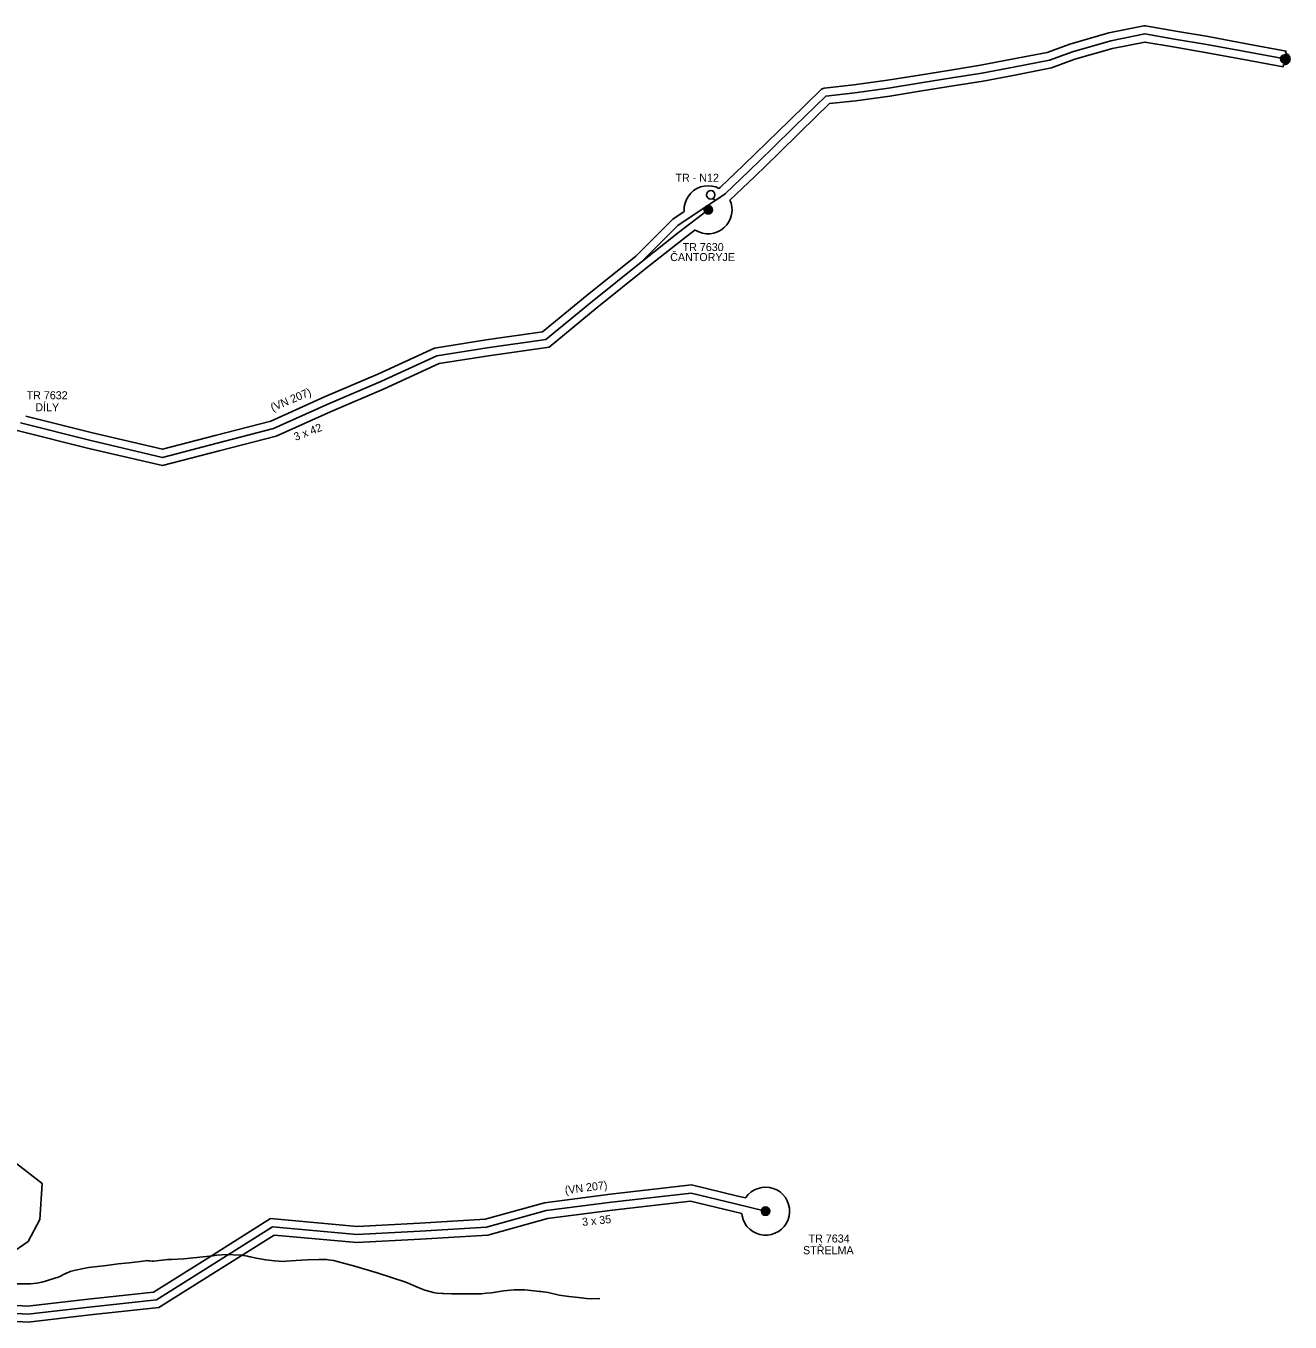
# Model space of a CAD drawing. Extents: x -439095 to -431527, y -1129525 to -1119219.
# Drawn here: x -436616 to -435036, y -1124332 to -1122712 of the extents above; entities that cross this region are included whole.
import ezdxf

# ---------------------------------------------------------------- set-up
doc = ezdxf.new("R2010")
doc.units = 0
for name, color, linetype in [('Hranice reseneho uzemi', 7, 'Continuous'), ('UZEMNI REZERVA', 7, 'Continuous'), ('Vrstva 11', 7, 'Continuous'), ('Vrstva 13', 7, 'Continuous'), ('Vrstva 19', 7, 'Continuous'), ('Vrstva 21', 7, 'Continuous'), ('ZU', 7, 'Continuous')]:
    doc.layers.add(name, color=color, linetype=linetype)

msp = doc.modelspace()

# ---------------------------------------------------------------- linework, layer by layer
at = {"layer": 'Hranice reseneho uzemi'}
msp.add_line((-435755, -1122930.5), (-435757.4, -1122927.6), dxfattribs=at)
for points in [[(-436622.9, -1123208.4), (-436534.9, -1123230.5), (-436445.4, -1123251.4), (-436377.2, -1123233.7), (-436306.5, -1123215.5), (-436238.7, -1123184.8), (-436172.3, -1123156.7), (-436102.5, -1123124.5), (-436039.5, -1123114.6), (-435966.2, -1123104.2), (-435908.5, -1123056.6), (-435847.3, -1123007.3), (-435845.2, -1123005.2), (-435801.3, -1122961.6), (-435742.2, -1122921.9), (-435712.2, -1122893.3), (-435683.2, -1122864.8), (-435655, -1122837.5), (-435616.5, -1122799.8), (-435616.3, -1122799.8), (-435580.4, -1122795.7), (-435538, -1122789.9), (-435497.9, -1122783.5), (-435459.1, -1122777.2), (-435421.4, -1122771.3), (-435382, -1122763.7), (-435337, -1122755), (-435308.3, -1122744.4), (-435260.5, -1122730.7), (-435218, -1122722.2), (-435217.8, -1122722.2), (-435180.8, -1122728.6), (-435140.5, -1122735.3), (-435092.5, -1122744.2), (-435043.1, -1122753.5)], [(-435847.3, -1123007.3), (-435800.4, -1122970.3), (-435800.4, -1122970.3), (-435763.3, -1122942)], [(-436699.2, -1124317.2), (-436613.5, -1124322.2), (-436537, -1124313.4), (-436453, -1124304.5), (-436383.4, -1124260.8), (-436308, -1124213.1), (-436202.3, -1124222.7), (-436123.4, -1124218.6), (-436040.6, -1124213.5), (-435966.1, -1124192.9), (-435884.3, -1124182.3), (-435784.9, -1124171), (-435729.4, -1124184.3), (-435729.4, -1124184.3), (-435691.8, -1124193.6), (-435691.5, -1124193.6), (-435691.5, -1124193.7)]]:
    msp.add_lwpolyline(points, dxfattribs=at)
at = {"layer": 'UZEMNI REZERVA'}
for points in [[(-436726.1, -1124283.9), (-436724.3, -1124276.9), (-436695.8, -1124271.9), (-436635.9, -1124247.3), (-436613.3, -1124231.5), (-436598.6, -1124204.1), (-436595.7, -1124158.9), (-436642.5, -1124122.7), (-436670.9, -1124104.1), (-436665.5, -1124056.1), (-436673.1, -1124038.1), (-436655, -1123989.1)], [(-436627.1, -1124284.4), (-436610.3, -1124284.5), (-436602.4, -1124283.6), (-436596.3, -1124282.3), (-436591.7, -1124281.1), (-436587.8, -1124279.8), (-436574.5, -1124275.5), (-436566.5, -1124271.7), (-436566.1, -1124271.5), (-436560.6, -1124269.2), (-436554, -1124267.3), (-436546, -1124265.6), (-436537.6, -1124264.2), (-436515.1, -1124261.4), (-436500.6, -1124259.6), (-436486.8, -1124258), (-436473, -1124256.5), (-436464.1, -1124255.4), (-436463.4, -1124255.5), (-436461.3, -1124255.7), (-436458.2, -1124256.2), (-436456.2, -1124255.9), (-436439, -1124254.2), (-436434.2, -1124253.9), (-436418.6, -1124253), (-436382.6, -1124249.3), (-436377.5, -1124248.8), (-436365.2, -1124247.9), (-436348.7, -1124248.4), (-436346.8, -1124248.7), (-436339.1, -1124249.9), (-436336, -1124250.7), (-436335.2, -1124250.8), (-436328.3, -1124252.4), (-436316.2, -1124254.6), (-436305.4, -1124255.8), (-436293.8, -1124256.6), (-436290.4, -1124256.3), (-436290.4, -1124256.3), (-436278.2, -1124255.4), (-436278.1, -1124255.4), (-436271.5, -1124254.9), (-436264.3, -1124254.4), (-436250, -1124254.2), (-436246.5, -1124254.2), (-436240.2, -1124254.1), (-436238.3, -1124254.3), (-436231.6, -1124255.2), (-436206.7, -1124261.8), (-436177.2, -1124270.8), (-436175.9, -1124271.2), (-436141.1, -1124282.5), (-436125.7, -1124289.1), (-436117.6, -1124292.2), (-436109.7, -1124294.6), (-436107.1, -1124295.1), (-436102.1, -1124296.1), (-436095.7, -1124296.7), (-436093.9, -1124296.6), (-436084.2, -1124296.9), (-436072.3, -1124297), (-436060.2, -1124297.1), (-436047.2, -1124297), (-436040.5, -1124296.2), (-436034.4, -1124295.5), (-436019.3, -1124293.3), (-436005.9, -1124292.1), (-435993, -1124292.1), (-435981.1, -1124293.3), (-435974.4, -1124294), (-435972.4, -1124294.2), (-435963.3, -1124295.3), (-435949.8, -1124298.4), (-435937.5, -1124300.4), (-435925.6, -1124301.5), (-435915.6, -1124302.6), (-435908.7, -1124303.1), (-435898.7, -1124302.7)]]:
    msp.add_lwpolyline(points, dxfattribs=at)
at = {"layer": 'Vrstva 11'}
for centre, radius in [((-435043.1, -1122753.4), 5.25), ((-435043.1, -1122753.4), 4.55), ((-435043.1, -1122753.4), 3.85), ((-435043.1, -1122753.4), 3.15), ((-435043.1, -1122753.4), 2.45), ((-435043.1, -1122753.4), 1.75), ((-435043.1, -1122753.4), 1.05), ((-435043.1, -1122753.4), 0.35), ((-435763.3, -1122942), 5.25), ((-435763.3, -1122942), 4.55), ((-435763.3, -1122942), 3.85), ((-435763.3, -1122942), 3.15), ((-435763.3, -1122942), 2.45), ((-435763.3, -1122942), 1.75), ((-435763.3, -1122942), 1.05), ((-435763.3, -1122942), 0.35), ((-435691.7, -1124193.6), 5.25), ((-435691.7, -1124193.6), 4.55), ((-435691.7, -1124193.6), 3.85), ((-435691.7, -1124193.6), 3.15), ((-435691.7, -1124193.6), 2.45), ((-435691.7, -1124193.6), 1.75), ((-435691.7, -1124193.6), 1.05), ((-435691.7, -1124193.6), 0.35)]:
    msp.add_circle(centre, radius, dxfattribs=at)
at = {"layer": 'Vrstva 19'}
msp.add_circle((-435760.3, -1122923.3), 5.25, dxfattribs=at)
at = {"layer": 'ZU'}
for points in [[(-435750.2, -1122915.2), (-435748.5, -1122914.1), (-435719.2, -1122886.1), (-435690.1, -1122857.7), (-435662, -1122830.3), (-435621.9, -1122791.1), (-435618.5, -1122789.9), (-435581.6, -1122785.8), (-435539.5, -1122780), (-435499.5, -1122773.6), (-435460.7, -1122767.3), (-435423.2, -1122761.4), (-435383.9, -1122753.9), (-435339.7, -1122745.4), (-435311.4, -1122734.9), (-435262.8, -1122721), (-435219, -1122712.2), (-435217, -1122712.2), (-435179.1, -1122718.8), (-435138.8, -1122725.5), (-435090.7, -1122734.4), (-435041.3, -1122743.6), (-435041.9, -1122746.7)], [(-435044.4, -1122760.4), (-435045, -1122763.3), (-435094.3, -1122754.1), (-435142.3, -1122745.2), (-435182.5, -1122738.5), (-435217.8, -1122732.3), (-435258.1, -1122740.5), (-435305.2, -1122753.9), (-435334.3, -1122764.7), (-435380.1, -1122773.6), (-435419.7, -1122781.1), (-435457.5, -1122787.1), (-435496.3, -1122793.4), (-435536.5, -1122799.8), (-435579.1, -1122805.6), (-435611.9, -1122809.3), (-435648, -1122844.6), (-435676.2, -1122872), (-435705.3, -1122900.5), (-435735.9, -1122929.7), (-435736.2, -1122929.9)], [(-435041.9, -1122746.7), (-435041, -1122746.9), (-435039.9, -1122747.4), (-435038.9, -1122748.1), (-435038, -1122749), (-435037.3, -1122750), (-435036.8, -1122751.1), (-435036.5, -1122752.3), (-435036.4, -1122753.5), (-435036.5, -1122754.7), (-435036.8, -1122755.9), (-435037.3, -1122757), (-435038, -1122758), (-435038.9, -1122758.9), (-435039.9, -1122759.6), (-435041, -1122760.1), (-435042.2, -1122760.4), (-435043.4, -1122760.5), (-435044.4, -1122760.4)], [(-435793.4, -1122944.3), (-435793.5, -1122943.2), (-435793.3, -1122938.4), (-435792.4, -1122933.6), (-435790.7, -1122929.1), (-435788.2, -1122924.9), (-435785.2, -1122921.2), (-435781.6, -1122918), (-435777.5, -1122915.4), (-435773.1, -1122913.5), (-435768.4, -1122912.4), (-435763.6, -1122912), (-435758.7, -1122912.4), (-435754.1, -1122913.5), (-435750.2, -1122915.2)], [(-435736.2, -1122929.9), (-435734.7, -1122933.6), (-435733.8, -1122938.4), (-435733.6, -1122943.2), (-435734.2, -1122948), (-435735.5, -1122952.6), (-435737.6, -1122957), (-435740.3, -1122960.9), (-435743.7, -1122964.4), (-435747.5, -1122967.3), (-435751.8, -1122969.6), (-435756.4, -1122971.1), (-435761.1, -1122971.9), (-435766, -1122971.9), (-435770.7, -1122971.1), (-435775.3, -1122969.6), (-435779.6, -1122967.3), (-435779.8, -1122967.2)], [(-436616, -1123199.8), (-436532.6, -1123220.8), (-436445.5, -1123241.1), (-436379.7, -1123224), (-436309.9, -1123206.1), (-436242.7, -1123175.6), (-436176.4, -1123147.6), (-436105.4, -1123114.8), (-436041, -1123104.7), (-435970.4, -1123094.7), (-435914.8, -1123048.8), (-435854, -1122999.8), (-435852.2, -1122998.1), (-435807.7, -1122953.9), (-435793.4, -1122944.3)], [(-435779.8, -1122967.2), (-435794.3, -1122978.3), (-435841.1, -1123015.1)], [(-435841.1, -1123015.1), (-435902.2, -1123064.3), (-435962.1, -1123113.7), (-436038.1, -1123124.5), (-436099.5, -1123134.1), (-436168.3, -1123165.9), (-436234.7, -1123193.9), (-436303.2, -1123225), (-436374.7, -1123243.4), (-436445.2, -1123261.7), (-436537.3, -1123240.2), (-436625.3, -1123218.1), (-436701.6, -1123199.4), (-436780.5, -1123180.9), (-436856.3, -1123162.6), (-436927.2, -1123141.4), (-436996.2, -1123119.6), (-437077.4, -1123093.6), (-437139.6, -1123075.7), (-437207.2, -1123055.3), (-437207.2, -1123055.2), (-437258, -1123039.8), (-437339.6, -1123005.9), (-437401, -1122981.1)], [(-436682.7, -1124308.1), (-436613.8, -1124312.2), (-436538.1, -1124303.4), (-436456.4, -1124294.8), (-436388.8, -1124252.3), (-436310.5, -1124202.8), (-436202.1, -1124212.6), (-436123.9, -1124208.6), (-436042.2, -1124203.6), (-435968.1, -1124183.1), (-435885.5, -1124172.4), (-435784.3, -1124160.8), (-435726.6, -1124174.7), (-435726.6, -1124174.7), (-435716.7, -1124177.1)], [(-435716.7, -1124177.1), (-435716.4, -1124176.6), (-435713.4, -1124172.8), (-435709.7, -1124169.6), (-435705.7, -1124167), (-435701.2, -1124165.1), (-435696.5, -1124164), (-435691.7, -1124163.6), (-435686.9, -1124164), (-435682.2, -1124165.1), (-435677.8, -1124167), (-435673.7, -1124169.6), (-435670.1, -1124172.8), (-435667, -1124176.6), (-435664.6, -1124180.7), (-435662.9, -1124185.2), (-435661.9, -1124190), (-435661.7, -1124194.8), (-435662.3, -1124199.6), (-435663.7, -1124204.2), (-435665.7, -1124208.6), (-435668.5, -1124212.6), (-435671.8, -1124216), (-435675.7, -1124218.9), (-435680, -1124221.2), (-435684.5, -1124222.7), (-435689.3, -1124223.5), (-435694.1, -1124223.5), (-435698.9, -1124222.7), (-435703.5, -1124221.2), (-435707.8, -1124218.9), (-435711.6, -1124216), (-435715, -1124212.6), (-435717.7, -1124208.6), (-435719.8, -1124204.2), (-435721.1, -1124199.6), (-435721.5, -1124196.6)], [(-435721.5, -1124196.6), (-435731.8, -1124194), (-435785.5, -1124181.1), (-435883.1, -1124192.3), (-435964.1, -1124202.7), (-436038.9, -1124223.4), (-436122.8, -1124228.6), (-436202.5, -1124232.7), (-436305.6, -1124223.4), (-436378.1, -1124269.2), (-436449.7, -1124314.2), (-436535.9, -1124323.3), (-436613.2, -1124332.2), (-436699.8, -1124327.2)]]:
    msp.add_lwpolyline(points, dxfattribs=at)

# ---------------------------------------------------------------- texts
at = {"layer": 'Vrstva 13'}
for s, p in [('TR 7630', (-435795.4, -1122993.6)), ('ČANTORYJE', (-435810.9, -1123006.1)), ('TR 7632', (-436615.1, -1123178.8)), ('DÍLY', (-436604.2, -1123193.8)), ('TR 7634', (-435638, -1124232.8)), ('STŘELMA', (-435644.9, -1124247.4))]:
    msp.add_text(s, height=10, dxfattribs=at).set_placement(p)
for s, rotation, p in [('(VN 207)', 22.6576, (-436307.8, -1123194.1)), ('3 x 42', 20.9507, (-436279, -1123230.9)), ('(VN 207)', 7.186, (-435942, -1124172.3)), ('3 x 35', 5.912, (-435920.5, -1124212.1))]:
    msp.add_text(s, height=10, rotation=rotation, dxfattribs=at).set_placement(p)
at = {"layer": 'Vrstva 21'}
msp.add_text('TR - N12', height=10, dxfattribs=at).set_placement((-435804.3, -1122906.9))

doc.saveas('drawing.dxf')
